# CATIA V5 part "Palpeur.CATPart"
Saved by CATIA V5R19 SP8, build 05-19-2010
Part number: CE5 Palpeur
Revision: ANY
Definition: UNKNOWN
Nomenclature: Palpeur
Source: Unknown
Bounding box of the stored display mesh (mm): x 0 to 30.051, y -0.3 to 11.7, z -3 to 3
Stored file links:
  D:\Documents\1_Travail\1 - ac-limoges.fr\ac-limoges.fr\Emmanuel Maynard - STI2D_Turgot\2 -2I2D\2_SEQUENCE_Serrure_Biométrique\5-Spé_ITEC\Serrure_Bio_Eleve\Palpeur.CATPart
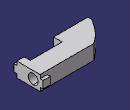
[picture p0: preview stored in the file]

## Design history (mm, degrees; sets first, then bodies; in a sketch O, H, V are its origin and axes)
Body1 "Extrusion4" (main body)
  Solid1: solid without history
